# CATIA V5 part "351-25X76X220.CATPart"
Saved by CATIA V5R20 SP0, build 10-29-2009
Part number: 351-25X76X220
Definition: NONE
Nomenclature: 351-25X76X220
Source: Unknown
Description: 351-25X76X220
Bounding box of the stored display mesh (mm): x -7 to 213, y -19 to 19, z -19 to 19
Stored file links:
  C:\Users\Utente\Desktop\IO LAVORO\3D X SITO CF\X SITO\PLASTICA\351\351-25X76X220.CATPart
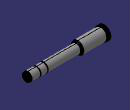
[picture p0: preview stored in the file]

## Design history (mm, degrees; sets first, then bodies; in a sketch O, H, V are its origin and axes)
Body1 "351-25X76X220" (main body)
  Solid1: solid without history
